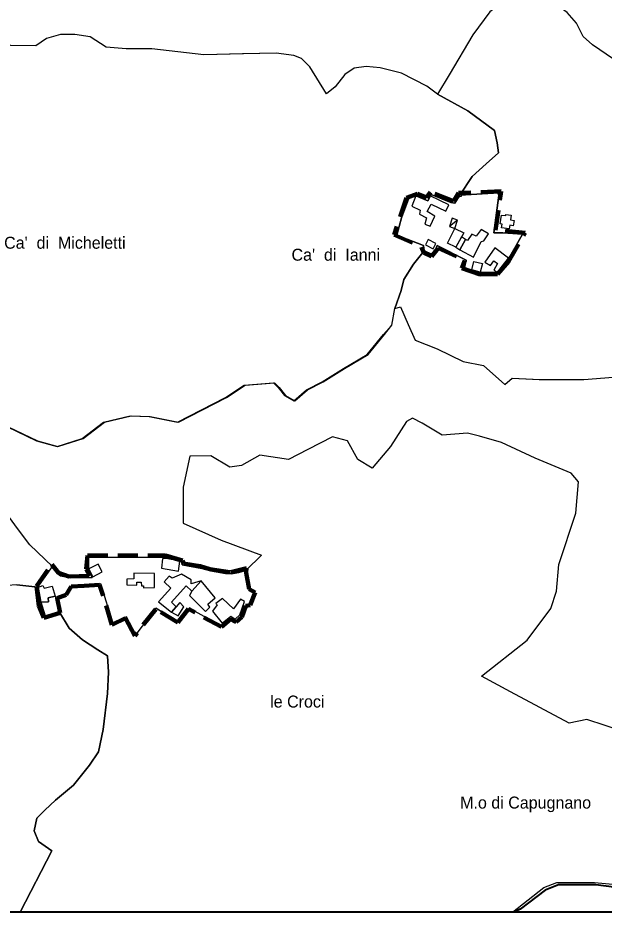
# Model space of a CAD drawing. Extents: x 652791 to 656927, y 889884 to 892405.
# Drawn here: x 655985 to 656474, y 889884 to 890630 of the extents above; entities that cross this region are included whole.
import ezdxf
from ezdxf.enums import TextEntityAlignment as Align

# ---------------------------------------------------------------- set-up
doc = ezdxf.new("R2010")
doc.units = 0
doc.header["$LTSCALE"] = 5.6
doc.header["$PDMODE"] = 32
doc.header["$PDSIZE"] = 2.8
doc.linetypes.add('MEDIUM_DASHED', pattern=[4.5, 3, -1.5])
for name, color, linetype, lineweight in [('1', 7, 'Continuous', 25), ('36', 7, 'Continuous', 25), ('37', 7, 'Continuous', 25), ('6', 7, 'Continuous', 25), ('61', 7, 'Continuous', 35), ('63', 7, 'Continuous', 40), ('7', 7, 'MEDIUM_DASHED', 100)]:
    doc.layers.add(name, color=color, linetype=linetype, lineweight=lineweight)
doc.layers.add('60', color=7, linetype='Continuous')

msp = doc.modelspace()

# ---------------------------------------------------------------- linework, layer by layer
at = {"layer": '1'}
msp.add_line((656351.51, 890461.61), (656344.76, 890456.42), dxfattribs=at)
msp.add_line((656351.51, 890461.61), (656344.76, 890456.42), dxfattribs=at)
for points in [[(656316.6, 890482.09), (656310.86, 890480.17), (656304.84, 890463.75), (656300.81, 890449.21), (656323.09, 890440.57), (656323.73, 890436.19), (656329.95, 890433.47)], [(656405.68, 890449.96), (656389.24, 890451.06), (656381.68, 890451.17), (656386.34, 890484.41), (656353.4, 890482.51), (656349.21, 890475.84), (656345.83, 890476.36), (656329.38, 890483.21), (656326.8, 890477.93), (656316.6, 890482.09)], [(656358.78, 890428.46), (656357.27, 890422.36), (656362.33, 890420.38), (656370.51, 890418.44), (656378.23, 890418.08), (656384.89, 890418.35), (656395.29, 890431.71), (656405.68, 890449.96)], [(656354.89, 890447.83), (656350.13, 890439.21), (656353.4, 890437.01)], [(656353.4, 890437.01), (656358.19, 890445.47), (656354.89, 890447.83)], [(656329.95, 890433.47), (656333.04, 890437.25), (656334.58, 890440.49), (656358.78, 890428.46)], [(656017.88, 890166.56), (656020.06, 890164.92), (656028.24, 890163.19), (656046.45, 890163.62), (656043.58, 890170.13), (656043.59, 890180.57), (656108.44, 890180.23), (656121.7, 890176.32), (656121.71, 890174.05), (656138.19, 890171.11), (656145.34, 890169.19)], [(656007.34, 890130.86), (656003.18, 890141.62), (656001.38, 890155.44), (656013.48, 890172.74), (656017.88, 890166.56)], [(656162.91, 890166.55), (656168.91, 890167.65), (656172.89, 890168.76), (656175.1, 890169.8), (656174.54, 890166.31), (656177.25, 890153.19), (656181.91, 890150.26), (656178.32, 890140.81), (656174.74, 890140.48), (656171.02, 890130.5), (656166.92, 890126.96), (656162.21, 890129.46), (656154.56, 890122.95), (656127.43, 890138.05), (656118.8, 890126.3)], [(656145.34, 890169.19), (656157.83, 890166.92), (656162.91, 890166.55)], [(656053.9, 890158.24), (656049.04, 890157.74), (656030.53, 890156.73), (656028.64, 890156.19)], [(656118.8, 890126.3), (656099.75, 890137.94), (656083.05, 890115.95), (656075.32, 890130.77), (656064.01, 890124.84), (656053.9, 890158.24)], [(656028.64, 890156.19), (656027.57, 890154.57), (656025.23, 890149.99), (656016.81, 890146.45), (656019.2, 890134.68), (656007.34, 890130.86)]]:
    msp.add_lwpolyline(points, dxfattribs=at)
for points in [[(656316.6, 890482.09), (656313.35, 890473.44), (656320.38, 890469.97), (656319.66, 890466.8), (656325.73, 890463.8), (656324.31, 890458.49), (656328.63, 890456.66), (656332.61, 890465.13), (656326.16, 890469.05), (656329.4, 890475.07), (656341.7, 890469.11), (656344.17, 890474.39), (656328.63, 890481.92), (656326.8, 890477.93)], [(656344.76, 890456.42), (656349.18, 890454.85), (656351.51, 890461.61), (656346.96, 890463.4)], [(656350.13, 890439.21), (656343.19, 890442.63), (656349.15, 890454.85), (656356.76, 890451.16)], [(656358.19, 890445.47), (656353.4, 890437.01), (656364.68, 890430.82), (656371.09, 890444.03), (656373.44, 890444.46), (656377.23, 890450.22), (656371.09, 890454), (656367.11, 890448.45), (656363.33, 890450.16), (656359.75, 890444.62)], [(656326.97, 890445.59), (656324.72, 890441.24), (656331.16, 890437.91), (656333.41, 890442.26)], [(656382.5, 890438.66), (656374.34, 890426.61), (656379.1, 890423.8), (656381.65, 890427.76), (656384.89, 890425.45), (656381.82, 890420), (656384.89, 890418.35), (656393.91, 890430.08)], [(656364.99, 890427.36), (656372.21, 890425.66), (656370.51, 890418.44), (656363.29, 890420.14)], [(656043.87, 890170.68), (656047.19, 890164.25), (656054.93, 890168.24), (656051.61, 890174.67)], [(656105.14, 890179.16), (656104.5, 890171.44), (656118.51, 890168.87), (656119.75, 890177.1), (656108.2, 890179.35)], [(656075.64, 890162.13), (656075.64, 890157.54), (656083.74, 890157.3), (656083.85, 890159.74), (656087.5, 890159.68), (656087.62, 890156.71), (656089.34, 890156.64), (656089.4, 890154.92), (656098.57, 890155.2), (656098.6, 890167.05), (656081.25, 890167.23), (656081.25, 890162.39)], [(656106.7, 890160.02), (656112.23, 890154.69), (656101.96, 890143.33), (656112.68, 890134.53), (656116.75, 890139.15), (656112.67, 890142.87), (656125.12, 890156.51), (656129.81, 890152.23), (656137.45, 890160.71), (656129.32, 890158.35), (656129.32, 890161.51), (656121.04, 890166.37), (656113.41, 890163.1), (656110.92, 890164.78)], [(656129.81, 890152.23), (656127.93, 890148.44), (656141.1, 890135.24), (656144.9, 890138.93), (656143.1, 890141.22), (656149.29, 890146.62), (656137.45, 890160.71), (656137.45, 890160.71)], [(656001.87, 890155.51), (656005.32, 890156.96), (656006.56, 890154.61), (656013.19, 890156.41), (656015.68, 890147.91), (656009.74, 890146.73), (656010.01, 890143.35), (656003.94, 890143)], [(656003.94, 890143), (656010.01, 890143.35), (656009.74, 890146.73), (656015.68, 890147.91), (656019.2, 890134.68), (656007.67, 890131.46)], [(656112.68, 890134.53), (656118.34, 890131.63), (656123.09, 890139.07), (656119.73, 890142.77), (656116.75, 890139.15)], [(656149.79, 890141.8), (656150.81, 890140.69), (656146.96, 890135.49), (656155.04, 890125.58), (656162.32, 890131.33), (656165.84, 890128.91), (656169.94, 890132.45), (656173.75, 890143.52), (656170.5, 890145.59), (656164.62, 890137.54), (656155.44, 890145.93)]]:
    msp.add_lwpolyline(points, close=True, dxfattribs=at)
at = {"layer": '36'}
for points in [[(656481.61, 890596.03), (656464.08, 890608.04), (656456.35, 890615.04), (656450.68, 890626.04), (656442.94, 890635.04), (656427.99, 890646.04), (656417.68, 890650.04), (656405.31, 890650.54), (656392.94, 890646.54), (656378.5, 890635.54), (656364.13, 890616.47), (656344.54, 890582.96), (656334.72, 890566.93), (656325.76, 890573.55), (656304.66, 890584.23), (656286.87, 890588.74), (656275.35, 890589.99), (656265.33, 890588.49), (656257.31, 890583.22), (656249.3, 890572.95), (656242.24, 890567.05), (656228.32, 890589.55)], [(656228.32, 890589.55), (656221.24, 890596.51), (656214.92, 890599.06), (656200.11, 890601.09), (656172.78, 890600.59), (656139.82, 890599.76), (656096.48, 890604.59), (656074.95, 890604.53), (656058.16, 890606.03), (656044.93, 890614.6), (656032.04, 890616.6), (656020.18, 890616.6), (656008.57, 890613.31), (655999.55, 890607.04), (655978.76, 890607.54)], [(655976.58, 890289.23), (656000.99, 890277.49), (656018.07, 890272.89), (656039.1, 890279.46), (656056.83, 890293.28), (656079.17, 890298.54), (656094.94, 890297.88), (656118.59, 890293.28), (656158.67, 890313.67), (656174.35, 890324.12), (656198.66, 890326.09), (656202.6, 890322.14), (656207.85, 890315.57), (656215.74, 890310.96), (656226.25, 890320.17), (656239.39, 890326.75), (656257.13, 890337.93), (656276.84, 890349.77), (656290.63, 890366.22), (656296.55, 890374.11), (656299.25, 890387.92), (656303.99, 890389.48), (656310.2, 890374.73), (656316.11, 890361.58), (656334.51, 890354.34), (656356.19, 890343.82), (656373.27, 890340.53), (656391.01, 890324.74), (656397.13, 890329.76), (656420.42, 890328.77), (656457.01, 890328.77), (656481.33, 890330.6)], [(656043.58, 890170.13), (656046.45, 890163.62), (656028.24, 890163.19), (656020.06, 890164.92), (656017.88, 890166.56), (656013.48, 890172.74), (655994.56, 890190.9), (655984.25, 890204.39), (655973.13, 890219.66), (655965.03, 890234.05), (655957.19, 890249.28), (655949.11, 890266.79), (655941.79, 890276.94), (655932.18, 890284.8), (655919.65, 890293.34), (655909.65, 890301.36), (655906.19, 890306.07), (655905.35, 890309.6), (655905.97, 890313.53), (655908.48, 890319.27)], [(656490.02, 890034.97), (656459.39, 890045.18), (656444.63, 890042.16), (656395.67, 890068.07), (656371.36, 890081.22), (656409.64, 890111.39), (656429.29, 890137.68), (656434.03, 890152.14), (656436.06, 890174.49), (656450.29, 890217.22), (656452.32, 890243.51), (656446.22, 890250.74), (656416.41, 890263.23), (656388.13, 890276.17), (656369.88, 890281.53), (656359.83, 890284.11), (656338.7, 890282.35), (656321.96, 890292.37), (656313.95, 890296.65), (656308.88, 890293.71), (656295.67, 890273.02), (656280.32, 890254.89), (656268.38, 890261.93), (656259.63, 890277.59), (656247.02, 890280.86), (656226.56, 890270.5), (656210.4, 890262.14), (656186.52, 890265.57), (656171.18, 890257.02), (656161.37, 890255.74), (656145.6, 890265.12), (656128.12, 890264.69), (656122.62, 890238.96), (656122.62, 890209.01), (656154.11, 890194.82), (656187.98, 890182.2)], [(656172.89, 890168.76), (656168.91, 890167.65), (656162.91, 890166.55), (656157.83, 890166.92), (656145.34, 890169.19), (656138.19, 890171.11), (656121.71, 890174.05), (656121.7, 890176.32), (656108.44, 890180.23), (656043.59, 890180.57), (656043.58, 890170.13)], [(656187.98, 890182.2), (656175.1, 890169.8), (656172.89, 890168.76)]]:
    msp.add_lwpolyline(points, dxfattribs=at)
at = {"layer": '37'}
msp.add_line((656386.34, 890484.41), (656381.68, 890451.17), dxfattribs=at)
for points in [[(656481.61, 890596.03), (656464.08, 890608.04), (656456.35, 890615.04), (656450.68, 890626.04), (656442.94, 890635.04), (656427.99, 890646.04), (656417.68, 890650.04), (656405.31, 890650.54), (656392.94, 890646.54), (656378.5, 890635.54), (656364.13, 890616.47), (656344.54, 890582.96), (656334.72, 890566.93)], [(656228.32, 890589.55), (656221.24, 890596.51), (656214.92, 890599.06), (656200.11, 890601.09), (656171.99, 890600.59), (656139.82, 890599.76), (656096.48, 890604.59), (656074.95, 890604.53), (656058.16, 890606.03), (656044.93, 890614.6), (656032.04, 890616.6), (656020.18, 890616.6), (656008.57, 890613.31), (655999.55, 890607.04), (655978.76, 890607.54), (655955.21, 890613.81), (655928.66, 890616.82), (655911.37, 890622.58), (655896.59, 890625.34), (655884.87, 890624.5), (655871.98, 890617.5), (655860.52, 890606.79), (655852.28, 890581.39)], [(656353.4, 890482.51), (656363.66, 890498.23), (656375.28, 890508.69), (656385.73, 890517.99), (656384.57, 890526.12), (656382.25, 890536.58), (656360.18, 890552.86), (656334.72, 890566.93), (656325.76, 890573.55), (656304.66, 890584.23), (656286.87, 890588.74), (656275.35, 890589.99), (656265.33, 890588.49), (656257.31, 890583.22), (656249.3, 890572.95), (656242.24, 890567.05), (656228.32, 890589.55)], [(656334.72, 890566.93), (656360.18, 890552.86), (656382.25, 890536.58), (656384.57, 890526.12), (656385.73, 890517.99), (656375.28, 890508.69), (656363.66, 890498.23), (656353.4, 890482.51), (656386.34, 890484.41)], [(656300.81, 890449.21), (656304.84, 890463.75), (656310.86, 890480.17), (656315.7, 890481.79)], [(656315.7, 890481.79), (656315.81, 890482.09), (656316.17, 890481.94)], [(656316.17, 890481.94), (656316.6, 890482.09), (656326.8, 890477.93), (656329.38, 890483.21)], [(656329.38, 890483.21), (656345.83, 890476.36), (656349.21, 890475.84), (656353.4, 890482.51)], [(656299.25, 890387.92), (656304.42, 890402.91), (656306.74, 890412.21), (656314.87, 890425), (656323.73, 890436.19), (656323.09, 890440.57), (656300.81, 890449.21)], [(656381.68, 890451.17), (656389.24, 890451.06), (656405.68, 890449.96), (656395.29, 890431.71), (656384.89, 890418.35), (656378.23, 890418.08), (656370.51, 890418.44), (656362.33, 890420.38)], [(656323.73, 890436.19), (656314.87, 890425), (656306.74, 890412.21), (656304.42, 890402.91), (656299.25, 890387.92), (656303.99, 890389.48), (656310.2, 890374.73), (656316.11, 890361.58), (656334.51, 890354.34), (656356.19, 890343.82), (656373.27, 890340.53), (656391.01, 890324.74), (656397.13, 890329.76), (656419.63, 890328.76), (656457.01, 890328.77), (656481.33, 890330.6)], [(656358.78, 890428.46), (656334.58, 890440.49), (656333.04, 890437.25), (656329.95, 890433.47), (656323.73, 890436.19)], [(656362.33, 890420.38), (656357.27, 890422.36), (656358.78, 890428.46)], [(655943.54, 890301.82), (655975.79, 890289.22), (656000.2, 890277.48), (656017.28, 890272.88), (656038.31, 890279.45), (656056.04, 890293.27), (656078.38, 890298.53), (656094.15, 890297.87), (656117.8, 890293.27), (656157.88, 890313.66), (656173.56, 890324.11), (656197.87, 890326.08), (656201.81, 890322.13), (656207.06, 890315.56), (656214.95, 890310.95), (656225.46, 890320.16), (656238.6, 890326.74), (656256.34, 890337.92), (656276.05, 890349.76), (656289.84, 890366.21), (656296.55, 890374.11), (656299.25, 890387.92)], [(656490.02, 890034.97), (656459.39, 890045.18), (656444.63, 890042.16), (656395.67, 890068.07), (656371.36, 890081.22), (656409.64, 890111.39), (656429.29, 890137.68), (656434.03, 890152.14), (656436.06, 890174.49), (656450.29, 890217.22), (656452.32, 890243.51), (656446.22, 890250.74), (656416.41, 890263.23), (656388.13, 890276.16), (656369.88, 890281.53), (656359.83, 890284.11), (656338.7, 890282.35), (656321.96, 890292.36), (656313.95, 890296.64), (656308.88, 890293.71), (656295.67, 890273.02), (656280.32, 890254.89), (656268.38, 890261.93), (656259.63, 890277.59), (656247.02, 890280.85)], [(656247.02, 890280.85), (656226.56, 890270.5), (656210.4, 890262.14), (656186.52, 890265.56), (656171.18, 890257.02), (656161.37, 890255.74), (656145.6, 890265.12), (656128.12, 890264.69), (656122.62, 890238.96), (656122.62, 890209.01), (656154.11, 890194.82), (656187.98, 890182.2), (656175.1, 890169.8), (656174.54, 890166.31), (656177.25, 890153.19), (656181.91, 890150.26), (656178.32, 890140.81), (656174.74, 890140.48), (656171.02, 890130.5), (656166.92, 890126.96), (656162.21, 890129.46), (656154.56, 890122.95), (656127.43, 890138.05), (656118.8, 890126.3)], [(656001.38, 890155.44), (655983.58, 890157.43), (655975.54, 890156.98), (655954.1, 890161), (655935.78, 890167.26), (655924.17, 890168.6), (655904.51, 890166.37), (655889.77, 890165.92), (655875.02, 890167.26), (655866.98, 890171.73), (655865.64, 890176.2), (655865.64, 890182.46), (655871.69, 890193.57), (655863.29, 890192.4), (655857.95, 890210.78), (655853.15, 890213.11), (655849.31, 890210.78), (655843.75, 890209.73)], [(655983.58, 890157.43), (656001.38, 890155.44), (656013.48, 890172.74), (655994.56, 890190.9), (655984.25, 890204.39)], [(656053.9, 890158.24), (656049.04, 890157.74), (656030.53, 890156.73)], [(656099.75, 890137.94), (656083.05, 890115.95), (656083.05, 890115.95), (656075.32, 890130.77), (656064.01, 890124.84), (656053.9, 890158.24)], [(656007.34, 890130.86), (656003.18, 890141.62), (656001.38, 890155.44)], [(656030.53, 890156.73), (656028.64, 890156.19), (656027.57, 890154.57), (656025.23, 890149.99), (656016.81, 890146.45), (656019.2, 890134.68)], [(656051.22, 890103.35), (656038.51, 890111.58), (656027.3, 890121.3), (656019.2, 890134.68), (656007.34, 890130.86)], [(656019.2, 890134.68), (656027.3, 890121.3), (656038.51, 890111.58), (656051.22, 890103.35)], [(656118.8, 890126.3), (656104.74, 890134.7), (656099.75, 890137.94)], [(655986.5, 889884.41), (656013.06, 889935.64), (656001.89, 889943.31), (655998.15, 889952.29), (656000.39, 889962.76), (656007.12, 889969.49), (656016.09, 889977.71), (656031.04, 889990.43), (656044.49, 890006.88), (656051.97, 890018.1), (656055.7, 890036.79), (656059.44, 890066.71), (656060.19, 890084.66), (656059.44, 890098.12), (656051.22, 890103.35)], [(656051.22, 890103.35), (656059.44, 890098.12), (656060.19, 890084.66), (656059.44, 890066.71), (656055.7, 890036.79), (656051.97, 890018.1), (656044.49, 890006.88), (656031.04, 889990.43), (656016.09, 889977.71), (656007.12, 889969.49), (656000.39, 889962.76), (655998.15, 889952.29), (656001.89, 889943.31), (656013.06, 889935.64), (655986.5, 889884.41)], [(655986.5, 889884.41), (656397.42, 889884.41), (656423.4, 889904.82), (656434.46, 889909.24), (656465.67, 889909.24), (656481.08, 889907.59)], [(655809.21, 889885.01), (655815.56, 889885.31), (655822.41, 889889.4), (655826.92, 889885.37), (655827.32, 889884.41), (655986.5, 889884.41)]]:
    msp.add_lwpolyline(points, dxfattribs=at)
for p in [(656386.34, 890484.41), (656353.4, 890482.51)]:
    msp.add_point(p, dxfattribs=at)
at = {"layer": '6'}
msp.add_lwpolyline([(656387.15, 890458.59), (656388.22, 890466.01), (656391.68, 890465.51), (656391.83, 890466.5), (656396.28, 890465.86), (656395.71, 890461.9), (656398.68, 890461.48), (656398.04, 890457.02), (656395.07, 890457.45), (656394.65, 890454.48), (656388.21, 890455.4), (656388.64, 890458.37)], close=True, dxfattribs=at)
at = {"layer": '61', "lineweight": 40}
msp.add_lwpolyline([(654894.04, 892404.68), (656926.84, 892404.68), (656926.84, 889884.41), (654894.04, 889884.41)], close=True, dxfattribs=at)
at = {"layer": '63'}
msp.add_lwpolyline([(656481.92, 889905.15), (656466.96, 889907.04), (656435.75, 889907.04), (656424.69, 889902.62), (656403.64, 889886.75), (656398.79, 889884.41)], dxfattribs=at)
at = {"layer": '7'}
msp.add_lwpolyline([(656329.7, 890431.29), (656335.41, 890438.42), (656357.51, 890428.1), (656355.19, 890421.78), (656370.34, 890416.31), (656384.86, 890416.73), (656393.91, 890427.26), (656408.01, 890451.26), (656383.18, 890453.37), (656387.81, 890485.79), (656352.33, 890484.4), (656348.04, 890477.58), (656328.89, 890485.16), (656325.52, 890480.74), (656318.15, 890483.69), (656308.89, 890480.32), (656298.58, 890449.58), (656321.52, 890439.26), (656323.25, 890434.55)], close=True, dxfattribs=at)
for points in [[(656006.35, 890129.94), (656001.94, 890139.92), (656000, 890156.25), (656012.82, 890174.4), (656018.52, 890167.4), (656027.19, 890164.41), (656044.68, 890164.93), (656041.7, 890170.5), (656042.73, 890182.04), (656107.9, 890181.84), (656121.87, 890177.89), (656122.9, 890175.3), (656136.76, 890172.97), (656144.8, 890170.64), (656162.02, 890167.92), (656175.49, 890171.29), (656175.11, 890167.4), (656177.57, 890153.92), (656182.49, 890151.2), (656178.47, 890140.44), (656174.85, 890140.05), (656171.52, 890130.55), (656166.73, 890126.28), (656162.02, 890128.78), (656154.61, 890122.29), (656127.05, 890137.33), (656118.11, 890125.92)], [(656118.11, 890125.92), (656099.59, 890137.2), (656082.1, 890114.91), (656074.45, 890129.68), (656063.06, 890124.11), (656052.82, 890157.55), (656039.89, 890156.77), (656029.15, 890155.99), (656025, 890149.12), (656017.49, 890146.4), (656019.82, 890134.09), (656006.35, 890129.94)]]:
    msp.add_lwpolyline(points, dxfattribs=at)

# ---------------------------------------------------------------- texts
at = {"layer": '60'}
for s, p in [("Ca'  di  Micheletti", (656023.81, 890437.89)), ("Ca'  di  Ianni", (656249.91, 890427.88)), ('le Croci', (656217.78, 890055.08)), ('M.o di Capugnano', (656408.32, 889970.8))]:
    msp.add_text(s, height=10, dxfattribs=at).set_placement(p, align=Align.CENTER)

doc.saveas('drawing.dxf')
